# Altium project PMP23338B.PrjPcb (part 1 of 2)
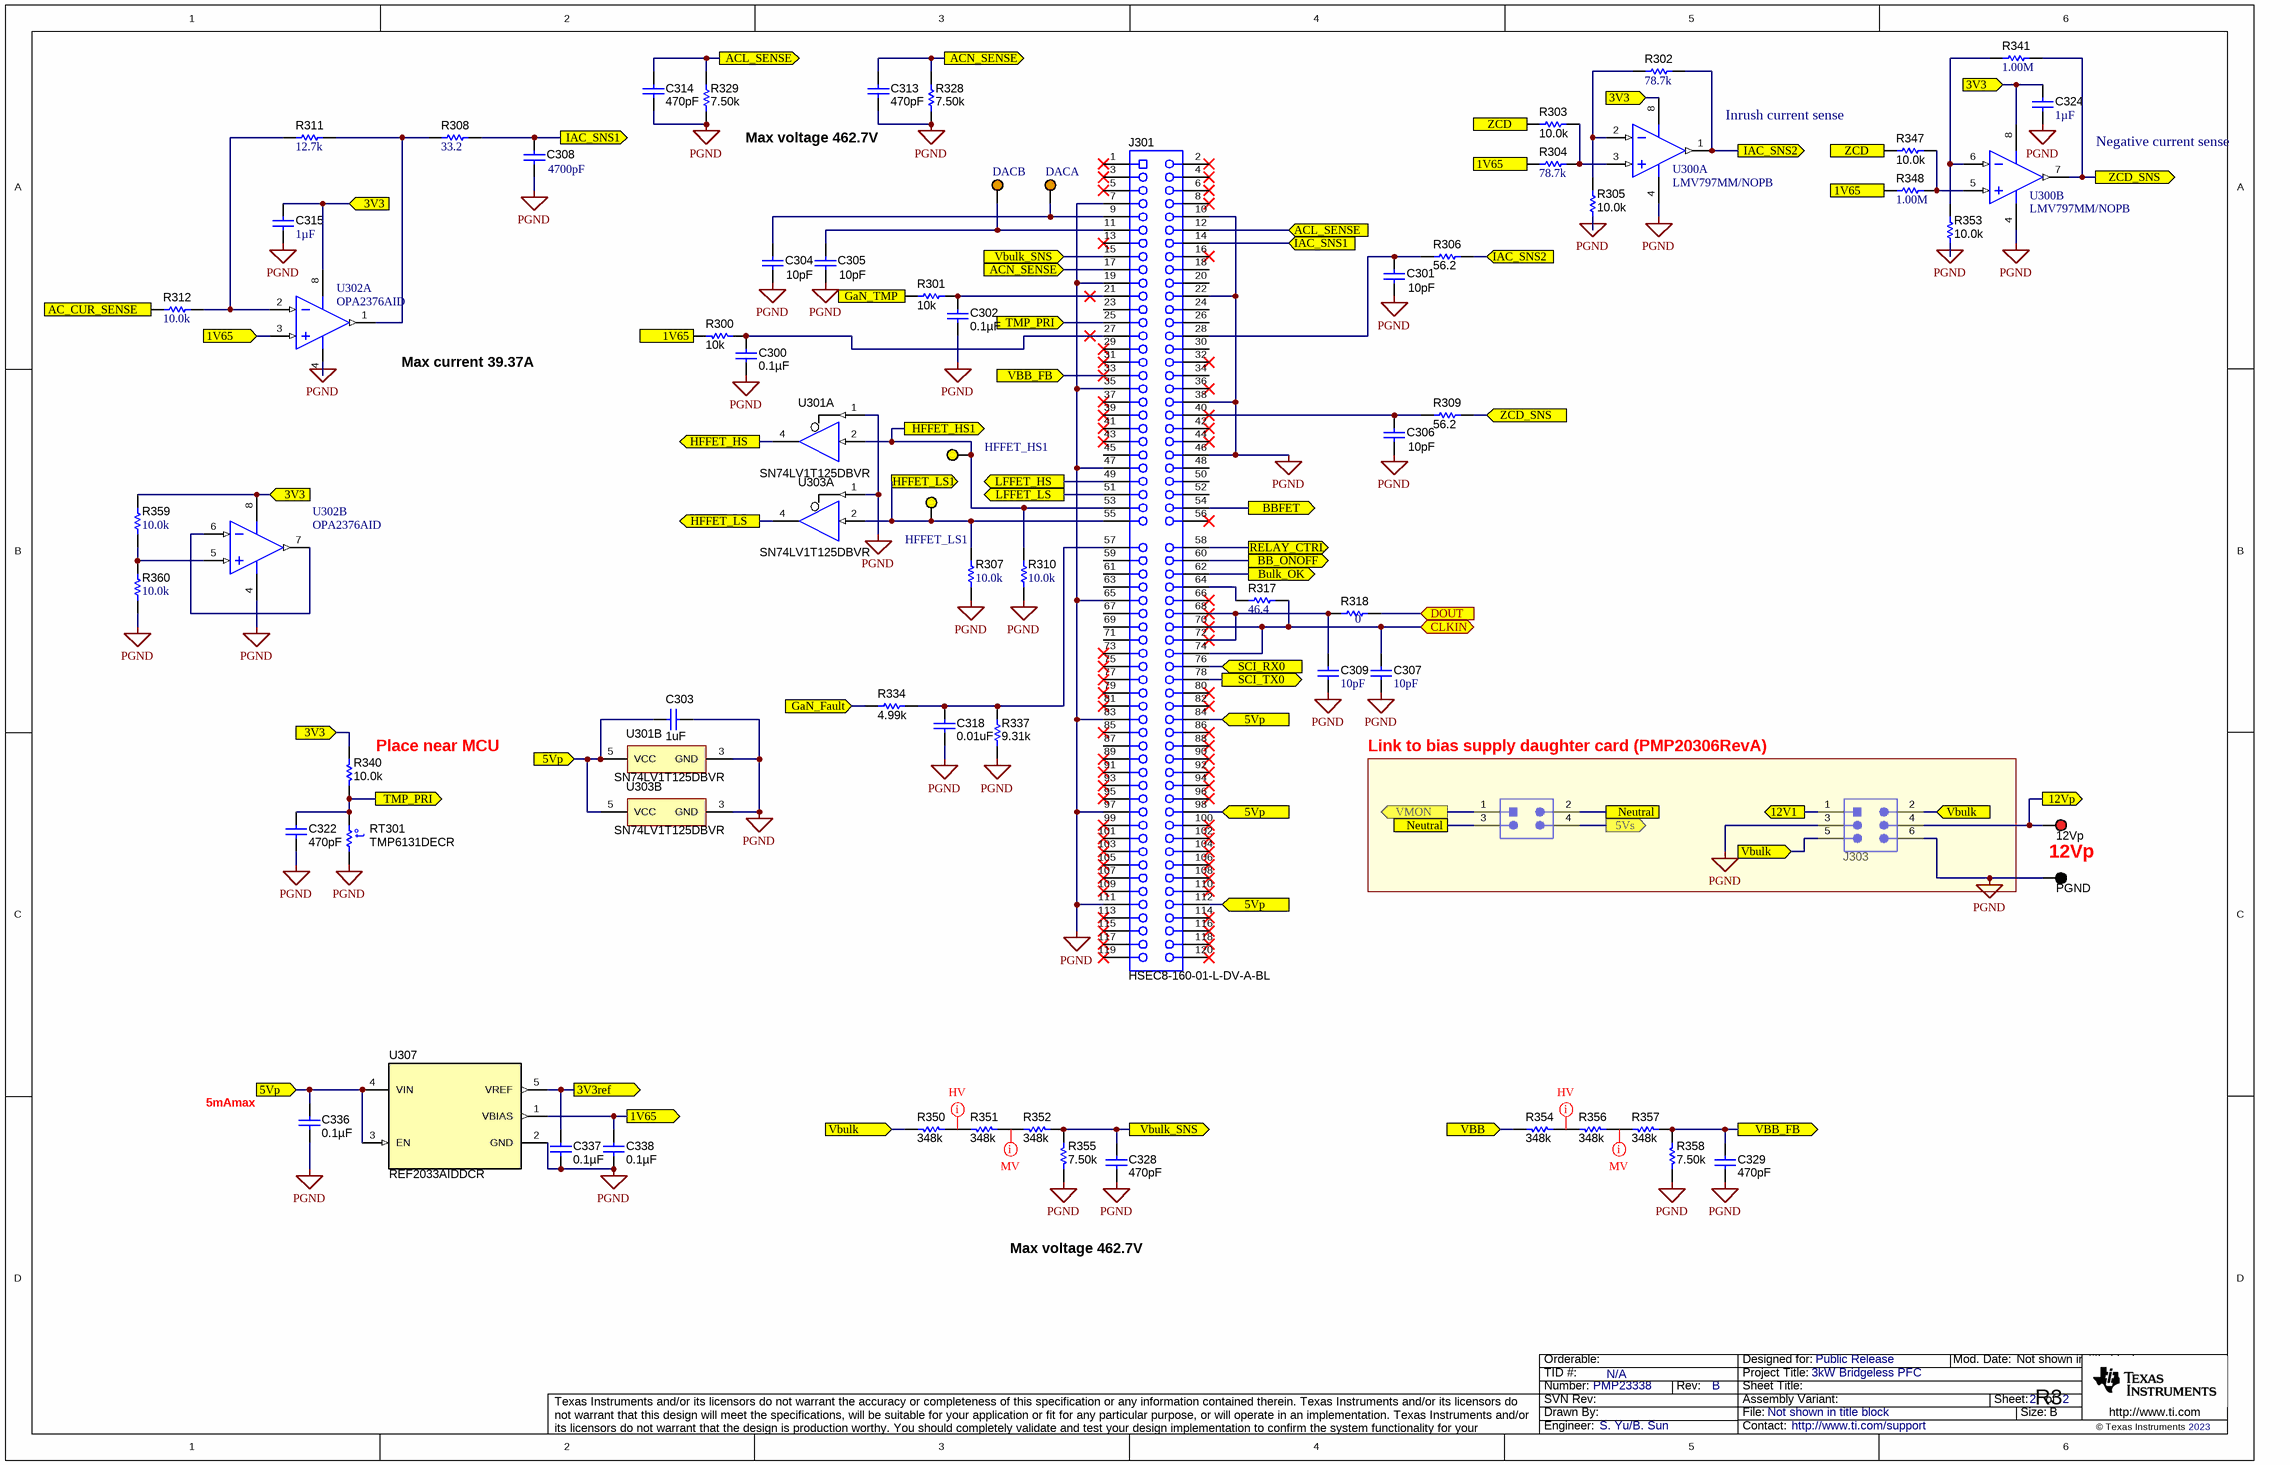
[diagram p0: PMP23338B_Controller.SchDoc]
CopyrightYear: 2023; PCB_Layout: S. Yu/B. Sun; PCB_Rev: B; PRJ_Customer: Public Release; PRJ_Engineer: S. Yu/B. Sun; PRJ_Number: PMP23338; PRJ_Title: 3kW Bridgeless PFC; SCH_Rev: B; TechSupport: http://www.ti.com/support; TID: N/A
2 sheets, 214 parts. Net scope: flat (ports and power ports of the same name join across sheets).
Board file: PMP23338B_PCB.PcbDoc
Sheets:
  PMP23338B_Controller.SchDoc
  PMP23338B_PFC.SchDoc

## Sheet PMP23338B_Controller.SchDoc
size 431 x 279 mm; Date: Not shown in title block; ApprovedBy: Not shown in title block; CheckedBy: Not shown in title block; Author: Not shown in title block; CompanyName: Not shown in title block; Engineer: Not shown in title block; Organization: Not shown in title block; Address1: Not shown in title block; Address2: Not shown in title block; Address3: Not shown in title block; Address4: Not shown in title block; DocumentNumber: 2; Revision: Use project parameter SCH_Rev; SheetNumber: 2; SheetTotal: 2; PageSetup: Record=PageOptions¦CenterHorizontal=True¦CenterVertical=True¦PrintScale=1.00¦XCorrection=1.00¦YCorrection=1.00¦PrintKind=0¦BorderSize=5000000¦LeftOffset=0¦BottomOffset=0¦Orientation=2¦PaperLength=1000¦PaperWidth=1000¦Scale=100¦PaperSource=15¦PrintQuality=600¦MediaType=1¦DitherType=10¦PaperKind=Letter¦PrintScaleMode=1

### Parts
(Parts that share a designator on the sheet are numbered #1, #2 ... from top to bottom, then left to right.)
12Vp  5000  [Keystone5000]  (value not drawn)
C300  ValueDisplayed: 0.1µF  [0402]  (hidden comment: GRM155R60J104KA01D)
C301  ValueDisplayed: 10pF  [0402]  (hidden comment: 04025U100CAT2A)
C302  ValueDisplayed: 0.1µF  [0402]  (hidden comment: GRM155R60J104KA01D)
C303  ValueDisplayed: 1uF  [0603]  (hidden comment: C1608X7R1E105K080AB)
C304  ValueDisplayed: 10pF  [0402]  (hidden comment: 04025U100CAT2A)
C305  ValueDisplayed: 10pF  [0402]  (hidden comment: 04025U100CAT2A)
C306  ValueDisplayed: 10pF  [0402]  (hidden comment: 04025U100CAT2A)
C307  ValueDisplayed: 10pF  [0402]  (hidden comment: C0402C100C8GACTU)
C308  ValueDisplayed: 4700pF  [0402]  (hidden comment: GRM155R61H472KA01D)
C309  ValueDisplayed: 10pF  [0402]  (hidden comment: C0402C100C8GACTU)
C313  ValueDisplayed: 470pF  [0402]  (hidden comment: CGA2B2X7R1H471K050BA)
C314  ValueDisplayed: 470pF  [0402]  (hidden comment: CGA2B2X7R1H471K050BA)
C315  Cap_F: 1µF  [0603]  (hidden comment: C1608X7R1E105K080AB)
C318  ValueDisplayed: 0.01uF  [0402]  (hidden comment: GRM155R70J103KA01D)
C322  ValueDisplayed: 470pF  [0402]  (hidden comment: CGA2B2X7R1H471K050BA)
C324  ValueDisplayed: 1µF  [0402]  (hidden comment: CC0402MRX5R6BB105)
C328  ValueDisplayed: 470pF  [0402]  (hidden comment: CGA2B2X7R1H471K050BA)
C329  ValueDisplayed: 470pF  [0402]  (hidden comment: CGA2B2X7R1H471K050BA)
C336  ValueDisplayed: 0.1µF  [0603]  (hidden comment: 06033C104JAT2A)
C337  ValueDisplayed: 0.1µF  [0603]  (hidden comment: 06033C104JAT2A)
C338  ValueDisplayed: 0.1µF  [0603]  (hidden comment: 06033C104JAT2A)
DACA  5003  [Keystone5003]  (value not drawn)
DACB  5003  [Keystone5003]  (value not drawn)
HFFET_HS1  5004  [Keystone5004]  (value not drawn)
HFFET_LS1  5004  [Keystone5004]  (value not drawn)
J301  HSEC8-160-01-L-DV-A-BL  [controlCARD-120HSEC]
J302  PBC02DAAN  [Sullins_PxC02DAAN]  (value not drawn)
J303  PBC03DAAN  [Sullins_PBC03DAAN]  (value not drawn)
PGND#1  5001  [Keystone5001]  (value not drawn)
R300  value 10k  [0402]  (hidden comment: CRCW040210K0JNED)
R301  value 10k  [0402]  (hidden comment: CRCW040210K0JNED)
R302  ValueDisplayed: 78.7k  [0402]  (hidden comment: CRCW040278K7FKED)
R303  ValueDisplayed: 10.0k  [0402]  (hidden comment: ERJPA2F1002X)
R304  ValueDisplayed: 78.7k  [0402]  (hidden comment: CRCW040278K7FKED)
R305  ValueDisplayed: 10.0k  [0402]  (hidden comment: ERJPA2F1002X)
R306  ValueDisplayed: 56.2  [0402]  (hidden comment: CRCW040256R2FKED)
R307  ValueDisplayed: 10.0k  [0603]  (hidden comment: CRCW060310K0FKEA)
R308  ValueDisplayed: 33.2  [0402]  (hidden comment: CRCW040233R2FKED)
R309  ValueDisplayed: 56.2  [0402]  (hidden comment: CRCW040256R2FKED)
R310  ValueDisplayed: 10.0k  [0603]  (hidden comment: CRCW060310K0FKEA)
R311  ValueDisplayed: 12.7k  [0402]  (hidden comment: CRCW040212K7FKED)
R312  ValueDisplayed: 10.0k  [0402]  (hidden comment: ERJ-2RKF1002X)
R317  ValueDisplayed: 46.4  [0402]  (hidden comment: CRCW040246R4FKED)
R318  ValueDisplayed: 0  [0402]  (hidden comment: CRCW04020000Z0ED)
R328  ValueDisplayed: 7.50k  [0402]  (hidden comment: CRCW04027K50FKED)
R329  ValueDisplayed: 7.50k  [0402]  (hidden comment: CRCW04027K50FKED)
R334  ValueDisplayed: 4.99k  [0402]  (hidden comment: CRCW04024K99FKED)
R337  ValueDisplayed: 9.31k  [0402]  (hidden comment: CRCW04029K31FKED)
R340  ValueDisplayed: 10.0k  [0402]  (hidden comment: CRCW040210K0FKED)
R341  ValueDisplayed: 1.00M  [0402]  (hidden comment: CRCW04021M00FKED)
R347  ValueDisplayed: 10.0k  [0402]  (hidden comment: ERJPA2F1002X)
R348  ValueDisplayed: 1.00M  [0402]  (hidden comment: CRCW04021M00FKED)
R350  ValueDisplayed: 348k  [1206]  (hidden comment: RC1206FR-07348KL)
R351  ValueDisplayed: 348k  [1206]  (hidden comment: RC1206FR-07348KL)
R352  ValueDisplayed: 348k  [1206]  (hidden comment: RC1206FR-07348KL)
R353  ValueDisplayed: 10.0k  [0402]  (hidden comment: ERJPA2F1002X)
R354  ValueDisplayed: 348k  [1206]  (hidden comment: RC1206FR-07348KL)
R355  ValueDisplayed: 7.50k  [0402]  (hidden comment: CRCW04027K50FKED)
R356  ValueDisplayed: 348k  [1206]  (hidden comment: RC1206FR-07348KL)
R357  ValueDisplayed: 348k  [1206]  (hidden comment: RC1206FR-07348KL)
R358  ValueDisplayed: 7.50k  [0402]  (hidden comment: CRCW04027K50FKED)
R359  ValueDisplayed: 10.0k  [0402]  (hidden comment: ERJ-2RKF1002X)
R360  ValueDisplayed: 10.0k  [0402]  (hidden comment: ERJ-2RKF1002X)
RT301  TMP6131DECR  [DEC0002A]
U300  LMV797MM/NOPB  [DGK0008A_N]  (parts A,B of 2)
U301#1  SN74LV1T125DBVR  [DBV0005A_N]  (part A of 2)
U301#2  SN74LV1T125DBVR  [DBV0005A_N]  (part B of 2)
U302  OPA2376AID  [D0008A_N]  (parts A,B of 2)
U303#1  SN74LV1T125DBVR  [DBV0005A_N]  (part A of 2)
U303#2  SN74LV1T125DBVR  [DBV0005A_N]  (part B of 2)
U307  REF2033AIDDCR  [DDC0005A_N]

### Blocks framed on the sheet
Link to bias supply daughter card (PMP20306RevA): J302 J303

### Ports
1V65 (in), 1V65 (out), 3V3 (in), 3V3ref (out), 5Vp (in), 5Vs (out), 12V1 (out), 12Vp (out), AC_CUR_SENSE (in), ACL_SENSE (in), ACL_SENSE (out), ACN_SENSE (in), ACN_SENSE (out), BB_ONOFF (out), BBFET (out), Bulk_OK (out), CLKIN (bidir), DOUT (in), GaN_Fault (in), GaN_TMP (in), HFFET_HS1 (out), HFFET_HS (out), HFFET_LS1 (out), HFFET_LS (out), IAC_SNS1 (in), IAC_SNS1 (out), IAC_SNS2 (in), IAC_SNS2 (out), LFFET_HS (out), LFFET_LS (out), Neutral, RELAY_CTRL (out), SCI_RX0 (in), SCI_TX0 (out), TMP_PRI (in), TMP_PRI (out), VBB (in), VBB_FB (in), VBB_FB (out), Vbulk (in), Vbulk_SNS (in), Vbulk_SNS (out), VMON (out), ZCD (in), ZCD_SNS (in), ZCD_SNS (out)

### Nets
PGND: C300.1 C301.2 C302.1 C303.1 C304.2 C305.2 C306.2 C307.2 C308.2 C309.2 C313.2 C314.2 C315.2 C318.2 C322.2 C324.2 C328.2 C329.2 C336.1 C337.1 C338.1 J301.7 J301.10 J301.19 J301.22 J301.35 J301.38 J301.46 J301.47 J301.65 J301.83 J301.97 J301.111 J303.3 J303.6 PGND#1.1 R305.1 R307.1 R310.1 R328.1 R329.1 R337.1 R353.1 R355.1 R358.1 R360.1 RT301.1 U300.4(V-) U301#1.1(~{OE}) U301#2.3(GND) U302.4(V-) U303#1.1(~{OE}) U303#2.3(GND) U307.2(GND)
1V65: C338.2 R300.1 R304.1 R348.2 U302.3(IN_A+) U307.1(VBIAS) ; port 1V65
3V3: C315.1 C324.1 R340.1 R359.2 U300.8(V+) U302.8(V+) ; port 3V3
3V3ref: C337.2 U307.5(VREF) ; port 3V3ref
5Vp: C303.2 C336.2 J301.84 J301.98 J301.112 U301#2.5(VCC) U303#2.5(VCC) U307.3(EN) U307.4(VIN) ; port 5Vp
5Vs: J302.4 ; port 5Vs
12V1: J303.1 ; port 12V1
12Vp: 12Vp.1 J303.4 ; port 12Vp
AC_CUR_SENSE: R312.2 ; port AC_CUR_SENSE
ACL_SENSE: C314.1 J301.12 R329.2 ; port ACL_SENSE
ACN_SENSE: C313.1 J301.17 R328.2 ; port ACN_SENSE
AINN: J302.2 J302.3 ; port Neutral
BB_ONOFF: J301.60 ; port BB_ONOFF
BBFET: J301.54 ; port BBFET
Bulk_OK: J301.62 ; port Bulk_OK
CLKIN: C307.1 J301.70 J301.74 R317.1 ; port CLKIN
DOUT: R318.2 ; port DOUT
GaN_Fault: R334.1 ; port GaN_Fault
GaN_TMP: R301.1 ; port GaN_TMP
HFFET_HS: U301#1.4(Y) ; port HFFET_HS
HFFET_HS1: HFFET_HS1.1 J301.53 R310.2 U301#1.2(A) ; port HFFET_HS1
HFFET_LS: U303#1.4(Y) ; port HFFET_LS
HFFET_LS1: HFFET_LS1.1 J301.55 R307.2 U303#1.2(A) ; port HFFET_LS1
IAC_SNS1: C308.1 J301.14 R308.2 ; port IAC_SNS1
IAC_SNS2: R302.2 R306.2 U300.1(OUTA) ; port IAC_SNS2
LFFET_HS: J301.49 ; port LFFET_HS
LFFET_LS: J301.51 ; port LFFET_LS
RELAY_CTRL: J301.58 ; port RELAY_CTRL
SCI_RX0: J301.76 ; port SCI_RX0
SCI_TX0: J301.78 ; port SCI_TX0
TMP_PRI: C322.1 J301.25 R340.2 RT301.2 ; port TMP_PRI
VBB: R354.2 ; port VBB
VBB_FB: C329.1 J301.33 R357.1 R358.2 ; port VBB_FB
Vbulk: J303.2 J303.5 R350.2 ; port Vbulk
Vbulk_SNS: C328.1 J301.15 R352.1 R355.2 ; port Vbulk_SNS
VMON: J302.1 ; port VMON
ZCD: R303.1 R347.1 ; port ZCD
ZCD_SNS: R309.1 R341.2 U300.7(OUTB) ; port ZCD_SNS
NetC300_2: C300.2 J301.27 R300.2
NetC301_1: C301.1 J301.28 R306.1
NetC302_2: C302.2 J301.21 R301.2
NetC304_1: C304.1 DACA.1 J301.9
NetC305_1: C305.1 DACB.1 J301.11
NetC306_1: C306.1 J301.40 R309.2
NetC309_1: C309.1 J301.68 J301.72 R318.1
NetC318_1: C318.1 J301.57 R334.2 R337.2
NetJ301_64: J301.64 R317.2
NetR302_1: R302.1 R305.2 U300.2(INA-)
NetR303_2: R303.2 R304.2 U300.3(INA+)
NetR308_1: R308.1 R311.2 U302.1(OUT_A)
NetR311_1: R311.1 R312.1 U302.2(IN_A-)
NetR341_1: R341.1 R353.2 U300.6(INB-)
NetR347_2: R347.2 R348.1 U300.5(INB+)
NetR350_1: R350.1 R351.2
NetR351_1: R351.1 R352.2
NetR354_1: R354.1 R356.2
NetR356_1: R356.1 R357.2
NetR359_1: R359.1 R360.2 U302.5(IN_B+)
NetU302_6: U302.6(IN_B-) U302.7(OUT_B)

Not connected (* = marked no-connect by the designer): J301 1* 2* 3* 4* 5* 6* 8* 13* 16* 18 20 23 24 26 29* 30 31* 32* 34 36* 37* 39* 41* 42* 43* 44* 45 48 50 52 56* 59 61 63 66* 67 69 71 73* 75* 77* 79* 80* 81* 82* 85* 86* 87 88* 89* 90* 91* 92* 93* 94* 95* 96* 99* 100* 101* 102* 103* 104* 105* 106* 107* 108* 109* 110* 113* 114* 115* 116* 117* 118* 119* 120*

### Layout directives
net class MV: NetR351_1, NetR356_1
net class HV: NetR350_1, NetR354_1

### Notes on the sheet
- Max voltage 462.7V
- Inrush current sense
- Negative current sense
- Max current 39.37A
- (near R340) Place near MCU
- 12Vp
- (near C336) 5mAmax
- R3

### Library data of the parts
12Vp = 5000: Test Point, Miniature, Red, TH; Manufacturer: Keystone; CompType: Test Point Loop; ContactFinish: Silver; Green_Lifecycle: Active; Green_REACh: Passed
C300 C302 = GRM155R60J104KA01D: CAP, CERM, 0.1uF, 6.3V, +/-10%, X5R, 0402; Manufacturer: MuRata; Polarized: N; CompType: Capacitor; U/M: EA; Cap_F: 0.0000001; Tolerance_%: 10; Value1: Unknown; VDC_V: 6.3; TaMin_C: -55; TaMax_C: 85
C301 C304-C306 = CMP-0064911-2: CAP, CERM, 10 pF, 50 V,+/- 2.5%, C0G/NP0, AEC-Q200 Grade 1, 0402; Manufacturer: AVX; TaMin_C: -55°C; Polarized: N; SizeAreaWB_mm2: 3; Value1: Unknown; U/M: EA; Value: 10pF; TaMax_C: 125°C; SizeZ_mm: 0.6; SizeX_mm: 1; SizeY_mm: 0.5; Value2: 50V; AEC Qualified: Y; AEC Category: Q200
C303 = C1608X7R1E105K080AB: CAP, CERM, 1uF, 25V, +/-10%, X7R, 0603; Manufacturer: TDK; Polarized: N; CompType: Capacitor; U/M: EA; Cap_F: 0.000001; Tolerance_%: 10; Value1: Unknown; VDC_V: 25; TaMin_C: -55; TaMax_C: 125
C307 C309 = CMP-0064914-1: CAP, CERM, 10 pF, 10 V,+/- 2.5%, C0G/NP0, 0402; Manufacturer: Kemet; TaMin_C: -55°C; Polarized: N; SizeAreaWB_mm2: 3; Value1: Unknown; U/M: EA; Value: 10pF; TaMax_C: 125°C; SizeZ_mm: 0.6; SizeX_mm: 1; SizeY_mm: 0.5; Value2: 10V; AEC Category: Q200
C308 = CMP-0006616-2: CAP, CERM, 4700 pF, 50 V, +/- 10%, X5R, 0402; Manufacturer: MuRata; TaMin_C: -55°C; Polarized: N; SizeAreaWB_mm2: 3; Value1: Unknown; U/M: EA; Value: 4700pF; TaMax_C: 85°C; SizeZ_mm: 0.6; SizeX_mm: 1; SizeY_mm: 0.5; Value2: 50V; Cap_F: 4.7nF; AEC Category: Q200
C313 C314 C322 C328 C329 = CMP-0006320-2: CAP, CERM, 470 pF, 50 V, +/- 10%, X7R, AEC-Q200 Grade 1, 0402; Manufacturer: TDK; TaMin_C: -55°C; ESR_ohm: 4.96489; Polarized: N; SizeAreaWB_mm2: 3; Value1: 4.96489 ohm; U/M: EA; Value: 470pF; TaMax_C: 125°C; SizeZ_mm: 0.6; SizeX_mm: 1; SizeY_mm: 0.5; Value2: 50V; CompType: Capacitor; AEC Qualified: Y; IRMS_A: 2.28414dA; AEC Category: Q200
C315 = CMP-0007040-4: CAP, CERM, 1 uF, 25 V, +/- 10%, X7R, 0603; Manufacturer: TDK; TaMin_C: -55°C; Polarized: N; SizeAreaWB_mm2: 4.68; Value1: Unknown; U/M: EA; Value: 1uF; TaMax_C: 125°C; SizeZ_mm: 1; SizeX_mm: 1.6; SizeY_mm: 0.8; Value2: 25V; SizeArea_mm2: 1.28; AEC Category: Q200
C318 = GRM155R70J103KA01D: CAP, CERM, 0.01uF, 6.3V, +/-10%, X7R, 0402; Manufacturer: MuRata; Polarized: N; CompType: Capacitor; U/M: EA; Cap_F: 0.00000001; Tolerance_%: 10; Value1: Unknown; VDC_V: 6.3; TaMin_C: -55; TaMax_C: 125
C324 = CMP-0081457-1: CAP, CERM, 1 µF, 10 V,+/- 20%, X5R, 0402; Manufacturer: Yageo America; TaMin_C: -55°C; Polarized: N; SizeAreaWB_mm2: 3; U/M: EA; Value: 1uF; TaMax_C: 85°C; SizeZ_mm: 0.6; SizeX_mm: 1; SizeY_mm: 0.5; Value2: 10V; AEC Category: Q200
C336-C338 = 06033C104JAT2A: CAP, CERM, 0.1uF, 25V, +/-5%, X7R, 0603; Manufacturer: AVX; Polarized: N; CompType: Capacitor; U/M: EA; Cap_F: 0.0000001; Tolerance_%: 5; ESR_Ohm: 0.05; Value1: 0.05 ohm; VDC_V: 25; TaMin_C: -55; TaMax_C: 125
DACA DACB = CMP-0055140-2: Test Point, Miniature, Orange, TH; Manufacturer: Keystone Electronics; Green_Lifecycle: Active; ContactFinish: Silver; CNHeader: FALSE; CT: TRUE; Green_REACh: Passed
HFFET_HS1 HFFET_LS1 = CMP-0055141-1: Test Point, Miniature, Yellow, TH; Manufacturer: Keystone; CNHeader: FALSE; Green_Lifecycle: Active; Green_REACh: Passed; ContactFinish: Silver; CT: TRUE
J301 = controlCARD-120HSEC: C2000 controlCARD-120HSEC connector, SMT; Manufacturer: Samtec; SymbolCreator: a0412235; Note: The pin numbering does not match Samtec datasheet
J302 = PBC02DAAN: Header, 2.54mm, 2x2, Gold, TH; Manufacturer: Sullins Connector Solutions; SymbolCreator: a0412235; U/M: EA
J303 = PBC03DAAN: Header, 100mil, 3x2, Gold, TH; Manufacturer: Sullins Connector Solutions; SymbolCreator: a0412235; U/M: EA
PGND#1 = 5001: Test Point, Miniature, Black, TH; Manufacturer: Keystone; CompType: Test Point Loop; ContactFinish: Silver; Green_Lifecycle: Active; Green_REACh: Passed
R300 R301 = CRCW040210K0JNED: RES, 10k ohm, 5%, 0.063W, 0402; Manufacturer: Vishay-Dale; CompType: Resistor; Res_ohm: 10000; Value_Code: 10k0; Tolerance_%: 5; Power_W: 0.063; VDC_V: 50; TempCo: 200 ppm/C; EIA_Code: E24; U/M: EA
R302 R304 = CMP-0026551-2: RES, 78.7 k, 1%, 0.063 W, AEC-Q200 Grade 0, 0402; Manufacturer: Vishay-Dale; Power_W: 63mW; TempCo: 100 ppm/C; Value_Code: 78k7; Value: 78.7k; EIA_Code: E96; SizeX_mm: 1; SizeY_mm: 0.5; SizeZ_mm: 0.6; Value2: 0.063W; AEC Qualified: Y; VDC_V: 50V; AEC Category: Q200; AEC Grade: 0
R303 R305 R347 R353 = CMP-0078779-1: RES, 10.0 k, 1%, 0.2 W, AEC-Q200 Grade 0, 0402; Manufacturer: Panasonic; Value_Code: 10k0; SizeArea_mm2: 0.5; AEC Qualified: Y; AEC Category: Q200; Res_ohm: 10k; Value: 10.0k; SizeZ_mm: 0.6; EIA_Code: E96; TempCo: 100 ppm/C; AEC Grade: 0; Power_W: 200mW; VDC_V: 50V; Value2: 0.2W; SizeX_mm: 1
R306 R309 = CMP-0026454-2: RES, 56.2, 1%, 0.063 W, AEC-Q200 Grade 0, 0402; Manufacturer: Vishay-Dale; Power_W: 63mW; TempCo: 100 ppm/C; Value_Code: 56R2; Value: 56.2; EIA_Code: E96; SizeX_mm: 1; SizeY_mm: 0.5; SizeZ_mm: 0.6; Value2: 0.063W; AEC Qualified: Y; VDC_V: 50V; AEC Category: Q200; AEC Grade: 0
R307 R310 = CMP-0021998-4: RES, 10.0 k, 1%, 0.1 W, AEC-Q200 Grade 0, 0603; Manufacturer: Vishay-Dale; Power_W: 100mW; TempCo: 100 ppm/C; Value_Code: 10k0; Value: 10.0k; EIA_Code: E96; Res_ohm: 10k; SizeX_mm: 1.6; SizeY_mm: 0.8; SizeZ_mm: 1; Value2: 0.1W; SizeArea_mm2: 1.28; AEC Qualified: Y; VDC_V: 75V; AEC Category: Q200; AEC Grade: 0
R308 = CMP-0026299-2: RES, 33.2, 1%, 0.063 W, AEC-Q200 Grade 0, 0402; Manufacturer: Vishay-Dale; Power_W: 63mW; TempCo: 100 ppm/C; Value_Code: 33R2; Value: 33.2; EIA_Code: E96; SizeX_mm: 1; SizeY_mm: 0.5; SizeZ_mm: 0.6; Value2: 0.063W; AEC Qualified: Y; VDC_V: 50V; AEC Category: Q200; AEC Grade: 0
R311 = CMP-0025993-3: RES, 12.7 k, 1%, 0.063 W, AEC-Q200 Grade 0, 0402; Manufacturer: Vishay-Dale; Power_W: 63mW; TempCo: 100 ppm/C; Value_Code: 12k7; Value: 12.7k; EIA_Code: E96; SizeX_mm: 1; SizeY_mm: 0.5; SizeZ_mm: 0.6; Value2: 0.063W; AEC Qualified: Y; VDC_V: 50V; AEC Category: Q200; AEC Grade: 0
R312 R359 R360 = CMP-0026658-1: RES, 10.0 k, 1%, 0.1 W, 0402; Manufacturer: Panasonic; Power_W: 100mW; TempCo: 100 ppm/C; Value_Code: 10k0; U/M: EA; Value: 10.0k; EIA_Code: E96; Res_ohm: 10k; SizeX_mm: 1; SizeY_mm: 0.5; SizeZ_mm: 0.6; Value2: 0.1W; VDC_V: 50V; AEC Category: Q200
R317 = CMP-0026392-2: RES, 46.4, 1%, 0.063 W, AEC-Q200 Grade 0, 0402; Manufacturer: Vishay-Dale; Power_W: 63mW; TempCo: 100 ppm/C; Value_Code: 46R4; Value: 46.4; EIA_Code: E96; SizeX_mm: 1; SizeY_mm: 0.5; SizeZ_mm: 0.6; Value2: 0.063W; AEC Qualified: Y; VDC_V: 50V; AEC Category: Q200; AEC Grade: 0
R318 = CMP-0026822-3: RES, 0, 5%, 0.063 W, AEC-Q200 Grade 0, 0402; Manufacturer: Vishay-Dale; Power_W: 63mW; TempCo: 200 ppm/C; Value_Code: 0000; Value: 0; EIA_Code: E24; SizeX_mm: 1; SizeY_mm: 0.5; SizeZ_mm: 0.6; Value2: 0.063W; AEC Qualified: Y; VDC_V: 50V; AEC Category: Q200
R328 R329 R355 R358 = CRCW04027K50FKED: RES, 7.50 k, 1%, 0.063 W, 0402; Manufacturer: Vishay-Dale; CompType: Resistor; Value: 7.50k; Res_ohm: 7500; Value_Code: 7k50; Tolerance_%: 1; Power_W: 0.063; Value2: 0.063W; VDC_V: 50; TempCo: 100 ppm/C; SizeArea_mm2: 0.5; SizeZ_mm: 0.6; EIA_Code: E96; U/M: EA; AEC Category: Q200
R334 = CRCW04024K99FKED: RES, 4.99 k, 1%, 0.063 W, 0402; Manufacturer: Vishay-Dale; CompType: Resistor; Value: 4.99k; Res_ohm: 4990; Value_Code: 4k99; Tolerance_%: 1; Power_W: 0.063; Value2: 0.063W; VDC_V: 50; TempCo: 100 ppm/C; SizeArea_mm2: 0.5; SizeZ_mm: 0.6; EIA_Code: E96; U/M: EA; AEC Category: Q200
R337 = CRCW04029K31FKED: RES, 9.31 k, 1%, 0.063 W, 0402; Manufacturer: Vishay-Dale; CompType: Resistor; Value: 9.31k; Res_ohm: 9310; Value_Code: 9k31; Tolerance_%: 1; Power_W: 0.063; Value2: 0.063W; VDC_V: 50; TempCo: 100 ppm/C; SizeArea_mm2: 0.5; SizeZ_mm: 0.6; EIA_Code: E96; U/M: EA; AEC Category: Q200
R340 = CRCW040210K0FKED: RES, 10.0 k, 1%, 0.063 W, 0402; Manufacturer: Vishay-Dale; CompType: Resistor; Value: 10.0k; Res_ohm: 10000; Value_Code: 10k0; Tolerance_%: 1; Power_W: 0.063; Value2: 0.063W; VDC_V: 50; TempCo: 100 ppm/C; SizeArea_mm2: 0.5; SizeZ_mm: 0.6; EIA_Code: E96; U/M: EA; AEC Category: Q200
R341 R348 = CMP-0026100-2: RES, 1.00 M, 1%, 0.063 W, AEC-Q200 Grade 0, 0402; Manufacturer: Vishay-Dale; Power_W: 63mW; TempCo: 100 ppm/C; Value_Code: 1M00; Value: 1.00Meg; EIA_Code: E96; Res_ohm: 1M; SizeX_mm: 1; SizeY_mm: 0.5; SizeZ_mm: 0.6; Value2: 0.063W; AEC Qualified: Y; VDC_V: 50V; AEC Category: Q200; AEC Grade: 0
R350-R352 = CMP-0018215-2: RES, 348 k, 1%, 0.25 W, 1206; Manufacturer: Yageo America; Power_W: 250mW; TempCo: 100 ppm/C; U/M: EA; Value: 348k; EIA_Code: E96; SizeX_mm: 3.2; SizeY_mm: 1.6; SizeZ_mm: 1.35; Value2: 0.25W; SizeArea_mm2: 5.12; VDC_V: 200V; AEC Category: Q200
R354 R356 R357 = CMP-0018215-2: RES, 348 k, 1%, 0.25 W, 1206; Manufacturer: Yageo America; Power_W: 250mW; TempCo: 100 ppm/C; U/M: EA; Value: 348k; EIA_Code: E96; SizeX_mm: 3.2; SizeY_mm: 1.6; SizeZ_mm: 1.35; Value2: 0.25W; SizeArea_mm2: 5.12; CompType: Resistor; VDC_V: 200V; AEC Category: Q200
RT301 = CMP-0084566-1: Thermistor, DEC0002A (X1SON-2); Alternate Manufacturer: Texas Instruments; Alternate PartNumber: TMP6131DECT; CompType: IC; AEC Category: Q200; SizeX_mm: 1; AEC Qualified: N; SizeZ_mm: 0.5; SizeArea_mm2: 0.6; SizeAreaWB_mm2: 3.2
U300 = CMP-0068783-2: 17 MHz, Low Noise, CMOS Input, 1.8V Operational Amplifiers, DGK0008A (VSSOP-8); Manufacturer: Texas Instruments; CompType: IC; AEC Category: Q200; AEC Qualified: N; SizeAreaWB_mm2: 23.6; SizeArea_mm2: 14.7; SizeX_mm: 4.9; SizeY_mm: 3; SizeZ_mm: 1.1
U301#1 U301#2 U303#1 U303#2 = CMP-0051320-2: Single Power Supply, Single BUFFER GATE w/ 3-State Output (active low enable), DBV0005A (SOT-23-5); Manufacturer: Texas Instruments; Schmitt Trigger: No; Voltage(Nom)(V): 1.8,2.5,3.3,5.5; Output Drive (IOL/IOH)(Max)(mA): 8/-8; Bits(#): 1; F @ Nom Voltage(Max)(Mhz): 50; Output Type: CMOS; Input Type: TTL; VCC(Min)(V): 1.6; tpd @ Nom Voltage(Max)(ns): 14.5,9.5,8.0,6.5; 3-State Output: Yes; ICC @ Nom Voltage(Max)(mA): 0.01; Rating: Catalog; Logic: True; Special Features: 1.8V to 3.3V Up Translation,3.3V to 1.8V Down Translation,5V Input Tolerant; VCC(Max)(V): 5.5; AEC Category: Q200; AEC Qualified: N; CompType: IC; SizeAreaWB_mm2: 14.82; SizeArea_mm2: 8.12; SizeX_mm: 2.8; SizeY_mm: 2.9; SizeZ_mm: 1.45
U302 = CMP-0040811-1: Precision, Low Noise, Low Quiescent Current Operational Amplifier, 2 to 5.5 V, -40 to 125 degC, 8-pin SOIC (D8), Green (RoHS & no Sb/Br); Manufacturer: Texas Instruments; Total Supply Voltage(Min)(+5V is 5, +/-5V is 10): 2; Vn at 1kHz(Typ)(nV/rtHz): 7.5; CMRR(Min)(dB): 76; Sub Family: Low Input Bias Current Amp (<=10pA), Low Noise Amp (<=10nV/rtHz), Low Offset Voltage Amplifier (<=500uV), Low Supply Voltage Amplifier (<=2.7V), Precision Amplifier; Iq per channel(Max)(mA): 0.95; Total Supply Voltage(Max)(+5V is 5, +/-5V is 10): 5.5; Vio (25C)(Max)(mV): 0.025; IIB(Max)(pA): 10; Offset Drift(Typ)(uV/C): 0.32
U307 = CMP-0066190-1: Low-Drift, Low-Power, Dual-Output VREF and VREF/2 Voltage Reference, DDC0005A (SOT-23-T-5); Alternate PartNumber: REF2033AIDDCT; Alternate Manufacturer: Texas Instruments; SizeAreaWB_mm2: 14.82; U/M: EA; SizeZ_mm: 1.1; SizeX_mm: 2.8; SizeY_mm: 2.9; SizeArea_mm2: 8.12; CompType: IC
